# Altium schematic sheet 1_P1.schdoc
size 309 x 223 mm; Symbol: Sheet-Symbol_A4; Device: Sheet-Symbol_A4; @Project Name: MicroUSB_extender_FCB; @Page Count: 1; @Update Date: 2024-12-01; @Create Date: 2024-11-30; @Schematic Name: Schematic1; @Page No: 1; @Page Name: P1; Company: EasyEDA.com; Reviewed: EasyEDA; Version: V0.1; Page Size: A4; Part Number: JLCPCB-002; Drawn: EasyEDA; @Board Name: Board1; @Create Time: 23:09:21; @Update Time: 00:03:23
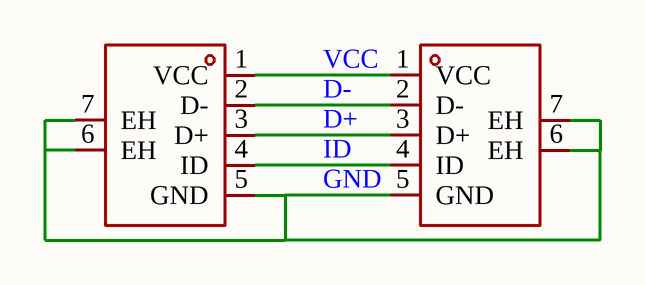
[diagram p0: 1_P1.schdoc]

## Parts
USB1  MICRO-ZD-103PWB  [MICRO-USB-SMD_ZD-103PWB]  (value not drawn)
USB2  MICRO-ZD-103PWB  [MICRO-USB-SMD_ZD-103PWB]  (value not drawn)

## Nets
D+: USB1.3(D+) USB2.3(D+)
D-: USB1.2(D-) USB2.2(D-)
GND: USB1.5(GND) USB1.6(EH) USB1.7(EH) USB2.5(GND) USB2.6(EH) USB2.7(EH)
ID: USB1.4(ID) USB2.4(ID)
VCC: USB1.1(VCC) USB2.1(VCC)

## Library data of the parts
USB1 USB2 = MICRO-ZD-103PWB: Connector Type:Micro-B Standard:USB 2.0 Gender:公 Number of Ports:1 Number of Contacts:5P Mounting Style:- Current Rating - Power (Max):- Contact Material:- Contact Plating:- Operating Temperature Range:- Operating Temperature Range:- Soldering Temperature; Manufacturer: HDGC(华德共创); Add into BOM: yes; Gender: 公; Number of Ports: 1; Number of Contacts: 5P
